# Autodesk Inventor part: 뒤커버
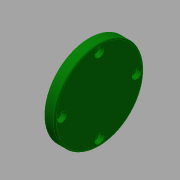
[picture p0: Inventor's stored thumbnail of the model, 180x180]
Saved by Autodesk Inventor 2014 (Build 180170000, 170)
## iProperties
Created: 2015-09
Part Number: 뒤커버
Material: 알루미늄 6061
Document SubType Name: Modeling
Designer: mduedu
Density: 2.71 g/cm^3
Mass: 54.0417 g
Surface Area: 84.9688 cm^2
Volume: 19.9416 cm^3
Appearance: 진녹색
Author: mduedu
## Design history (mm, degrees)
sketch "스케치1"
  geometry: L1 (-15.5, 47)-(-15.5, 78); L2 (-15.5, 78)-(-22.5, 78); L3 (-22.5, 78)-(-22.5, 63); L4 (-28.5, 63)-(-28.5, 47); L5 (-79.5, 39.5)-(-79.5, 54.5) reference; L6 (48.5, 54.5)-(48.5, 39.5) reference; L7 (-79.5, 47)-(48.5, 47); L8 (-22.5, 63)-(-28.5, 63); L9 (-28.5, 47)-(-15.5, 47); 1 further point
  constraints: 14 end point, 4 midpoint, 3 parallel, 1 collinear, 1 point on line, 1 vertical
  dimensions: "d6" = 62 diameter of L2 L7; "d7" = 7 distance of L1.end L2.end; "d8" = 32 diameter of L3.end L7; "d32" = 13 distance between parallel lines of L1 L4
revolve "회전1" sketch "스케치1" stored, may be unused: angle "d4" = 90 deg
sketch "스케치4"
  geometry: C1 r 31 at (0, 0) reference; 2 further points
  constraints: 1 coincident
hole "구멍3" sketch "스케치4" at (0, 0) diameter "d33" = 22; stored, may be unused: countersink angle "d37" = 90 deg, drill point angle "d39" = 0 deg; dims "d34" = 6, "d35" = 4, "d36" = 2, "d38" = 8
fillet "모깎기4" dims "d40" = 1
chamfer "모따기2" distance "d41" = 1; stored, may be unused: second distance "d42" = 2, angle "d43" = 45 deg
sketch "스케치6" dims "d56" = 52
  geometry: C1 r 31 at (0, 0) reference; 5 further points
  constraints: 2 vertical alignment, 1 coincident, 7 other
  dimensions: "d59" = 360 deg dimension on C1.centre point (0, 26) (derived)
hole "구멍4" sketch "스케치6" at (0, 26), (-26, 0), (0, -26), (26, 0) diameter "d49" = 3.4; stored, may be unused: countersink angle "d53" = 90 deg, drill point angle "d55" = 0 deg; dims "d50" = 6, "d51" = 6.5, "d52" = 3.4, "d54" = 8
fillet "모깎기5" dims "d61" = 3
node "솔리드1"
node "참조1"
node "참조2"
